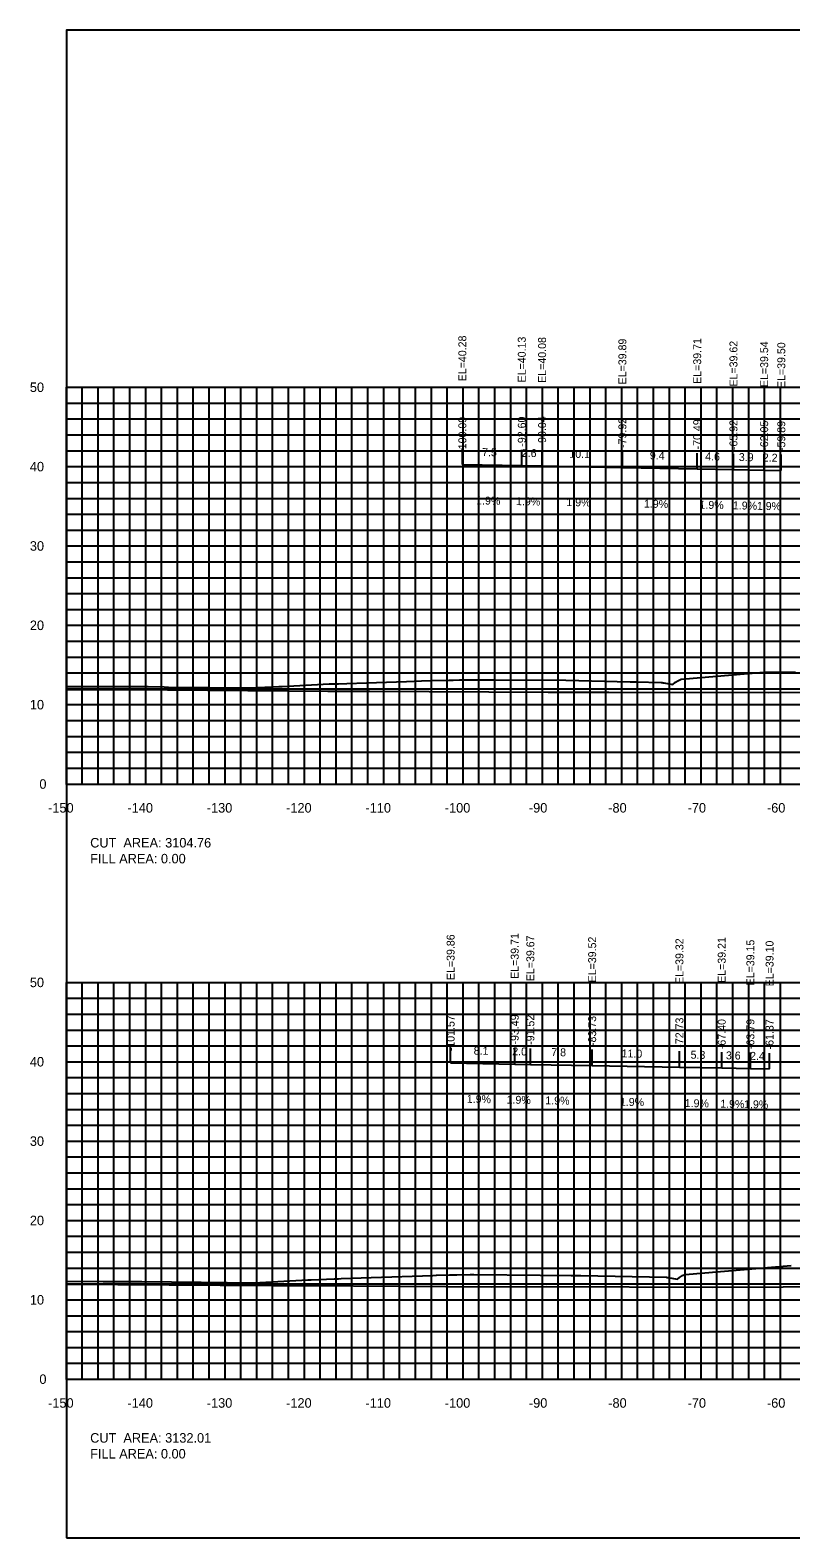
# Model space of a CAD drawing. Extents: x 1800880 to 1818864, y 245271 to 250560.
# Drawn here: x 1810398.3 to 1810494.1, y 250355.3 to 250545.3 of the extents above; entities that cross this region are included whole.
import ezdxf

# ---------------------------------------------------------------- set-up
doc = ezdxf.new("R2010")
doc.units = 0
for name, color, linetype in [('33', 7, 'Continuous'), ('ANNO-TXT', 7, 'Continuous'), ('CL-CNST', 7, 'Continuous'), ('DESIGN - DRAINAGE - Bridges', 7, 'Continuous'), ('DRAINAGETXT', 7, 'Continuous'), ('Level 37', 7, 'Continuous'), ('Level 46', 7, 'Continuous'), ('Level 62', 7, 'Continuous'), ('SHT-BDR', 7, 'Continuous')]:
    doc.layers.add(name, color=color, linetype=linetype)

msp = doc.modelspace()

# ---------------------------------------------------------------- linework, layer by layer
at = {"layer": 'CL-CNST'}
for points in [[(1810402.82, 250462.62), (1810403.63, 250462.62), (1810409.47, 250462.61), (1810412.41, 250462.6), (1810413.12, 250462.6), (1810415.15, 250462.55), (1810415.68, 250462.54), (1810425.94, 250462.42), (1810425.95, 250462.42), (1810426.04, 250462.43), (1810426.05, 250462.43), (1810429.6, 250462.62), (1810429.75, 250462.63), (1810430.02, 250462.63), (1810435.94, 250462.94), (1810436.28, 250462.94), (1810436.44, 250462.94), (1810437, 250462.96), (1810437.1, 250462.96), (1810438.18, 250462.99), (1810440.64, 250463.06), (1810445.67, 250463.25), (1810447.56, 250463.32), (1810448.75, 250463.37), (1810451.01, 250463.41), (1810451.53, 250463.42), (1810451.58, 250463.42), (1810452.39, 250463.44), (1810453.56, 250463.47), (1810456.87, 250463.45), (1810465.78, 250463.39), (1810473.87, 250463.21), (1810474.65, 250463.19), (1810477.79, 250463.12), (1810477.86, 250463.11), (1810477.94, 250463.1), (1810478.01, 250463.09), (1810478.07, 250463.08), (1810478.13, 250463.07), (1810479.24, 250462.88), (1810479.61, 250463.15), (1810479.87, 250463.34), (1810480.31, 250463.55), (1810480.35, 250463.55), (1810490.71, 250464.41), (1810494.71, 250464.43)], [(1810402.82, 250387.67), (1810407.47, 250387.64), (1810410.23, 250387.64), (1810412.32, 250387.63), (1810419.83, 250387.55), (1810426.39, 250387.46), (1810426.44, 250387.46), (1810433.27, 250387.82), (1810433.5, 250387.83), (1810433.67, 250387.83), (1810436.56, 250387.98), (1810436.93, 250387.98), (1810437.06, 250387.98), (1810437.1, 250387.98), (1810437.47, 250387.99), (1810441.25, 250388.11), (1810449.01, 250388.4), (1810449.44, 250388.41), (1810449.45, 250388.41), (1810451.11, 250388.45), (1810451.46, 250388.46), (1810451.71, 250388.46), (1810452.05, 250388.46), (1810453.72, 250388.5), (1810454.17, 250388.51), (1810462.55, 250388.43), (1810466.43, 250388.39), (1810467.65, 250388.37), (1810478.44, 250388.18), (1810478.48, 250388.17), (1810478.55, 250388.15), (1810478.61, 250388.14), (1810479.84, 250387.92), (1810480.11, 250388.12), (1810480.48, 250388.38), (1810480.79, 250388.53), (1810480.81, 250388.53), (1810494.17, 250389.64)]]:
    msp.add_lwpolyline(points, dxfattribs=at)
at = {"layer": 'DESIGN - DRAINAGE - Bridges'}
for p, q in [((1810402.76, 250500.32), (1810402.82, 250500.32)), ((1810402.82, 250450.32), (1810402.82, 250500.32)), ((1810402.76, 250490.32), (1810402.82, 250490.32)), ((1810402.76, 250480.32), (1810402.82, 250480.32)), ((1810402.76, 250470.32), (1810402.82, 250470.32)), ((1810402.76, 250460.32), (1810402.82, 250460.32)), ((1810402.76, 250450.32), (1810402.82, 250450.32)), ((1810402.82, 250450.32), (1810702.82, 250450.32)), ((1810402.82, 250450.26), (1810402.82, 250450.32)), ((1810412.82, 250450.26), (1810412.82, 250450.32)), ((1810422.82, 250450.26), (1810422.82, 250450.32)), ((1810432.82, 250450.26), (1810432.82, 250450.32)), ((1810442.82, 250450.26), (1810442.82, 250450.32)), ((1810452.82, 250450.26), (1810452.82, 250450.32)), ((1810462.82, 250450.26), (1810462.82, 250450.32)), ((1810472.82, 250450.26), (1810472.82, 250450.32)), ((1810482.82, 250450.26), (1810482.82, 250450.32)), ((1810492.82, 250450.26), (1810492.82, 250450.32)), ((1810402.76, 250425.32), (1810402.82, 250425.32)), ((1810402.82, 250375.32), (1810402.82, 250425.32)), ((1810402.76, 250415.32), (1810402.82, 250415.32)), ((1810402.76, 250405.32), (1810402.82, 250405.32)), ((1810402.76, 250395.32), (1810402.82, 250395.32)), ((1810402.76, 250385.32), (1810402.82, 250385.32)), ((1810402.76, 250375.32), (1810402.82, 250375.32)), ((1810402.82, 250375.32), (1810702.82, 250375.32)), ((1810402.82, 250375.26), (1810402.82, 250375.32)), ((1810412.82, 250375.26), (1810412.82, 250375.32)), ((1810422.82, 250375.26), (1810422.82, 250375.32)), ((1810432.82, 250375.26), (1810432.82, 250375.32)), ((1810442.82, 250375.26), (1810442.82, 250375.32)), ((1810452.82, 250375.26), (1810452.82, 250375.32)), ((1810462.82, 250375.26), (1810462.82, 250375.32)), ((1810472.82, 250375.26), (1810472.82, 250375.32)), ((1810482.82, 250375.26), (1810482.82, 250375.32)), ((1810492.82, 250375.26), (1810492.82, 250375.32))]:
    msp.add_line(p, q, dxfattribs=at)
at = {"layer": 'Level 37'}
for p, q in [((1810452.73, 250490.6), (1810452.73, 250492.6)), ((1810460.22, 250490.45), (1810460.22, 250492.45)), ((1810462.78, 250490.41), (1810462.78, 250492.41)), ((1810472.9, 250490.21), (1810472.9, 250492.21)), ((1810482.33, 250490.03), (1810482.33, 250492.03)), ((1810486.9, 250489.94), (1810486.9, 250491.94)), ((1810490.77, 250489.87), (1810490.77, 250491.87)), ((1810492.93, 250489.83), (1810492.93, 250491.83)), ((1810451.25, 250415.19), (1810451.25, 250417.19)), ((1810459.33, 250415.03), (1810459.33, 250417.03)), ((1810461.3, 250414.99), (1810461.3, 250416.99)), ((1810469.09, 250414.85), (1810469.09, 250416.85)), ((1810480.09, 250414.64), (1810480.09, 250416.64)), ((1810485.42, 250414.54), (1810485.42, 250416.54)), ((1810489.03, 250414.47), (1810489.03, 250416.47)), ((1810491.45, 250414.42), (1810491.45, 250416.42))]:
    msp.add_line(p, q, dxfattribs=at)
msp.add_lwpolyline([(1810402.82, 250355.32), (1810702.82, 250355.32), (1810702.82, 250545.32), (1810402.82, 250545.32)], close=True, dxfattribs=at)
at = {"layer": 'Level 46'}
for p, q in [((1810402.82, 250500.32), (1810702.82, 250500.32)), ((1810402.82, 250450.32), (1810402.82, 250500.32)), ((1810404.82, 250450.32), (1810404.82, 250500.32)), ((1810406.82, 250450.32), (1810406.82, 250500.32)), ((1810408.82, 250450.32), (1810408.82, 250500.32)), ((1810410.82, 250450.32), (1810410.82, 250500.32)), ((1810412.82, 250450.32), (1810412.82, 250500.32)), ((1810414.82, 250450.32), (1810414.82, 250500.32)), ((1810416.82, 250450.32), (1810416.82, 250500.32)), ((1810418.82, 250450.32), (1810418.82, 250500.32)), ((1810420.82, 250450.32), (1810420.82, 250500.32)), ((1810422.82, 250450.32), (1810422.82, 250500.32)), ((1810424.82, 250450.32), (1810424.82, 250500.32)), ((1810426.82, 250450.32), (1810426.82, 250500.32)), ((1810428.82, 250450.32), (1810428.82, 250500.32)), ((1810430.82, 250450.32), (1810430.82, 250500.32)), ((1810432.82, 250450.32), (1810432.82, 250500.32)), ((1810434.82, 250450.32), (1810434.82, 250500.32)), ((1810436.82, 250450.32), (1810436.82, 250500.32)), ((1810438.82, 250450.32), (1810438.82, 250500.32)), ((1810440.82, 250450.32), (1810440.82, 250500.32)), ((1810442.82, 250450.32), (1810442.82, 250500.32)), ((1810444.82, 250450.32), (1810444.82, 250500.32)), ((1810446.82, 250450.32), (1810446.82, 250500.32)), ((1810448.82, 250450.32), (1810448.82, 250500.32)), ((1810450.82, 250450.32), (1810450.82, 250500.32)), ((1810452.82, 250450.32), (1810452.82, 250500.32)), ((1810454.82, 250450.32), (1810454.82, 250500.32)), ((1810456.82, 250450.32), (1810456.82, 250500.32)), ((1810458.82, 250450.32), (1810458.82, 250500.32)), ((1810460.82, 250450.32), (1810460.82, 250500.32)), ((1810462.82, 250450.32), (1810462.82, 250500.32)), ((1810464.82, 250450.32), (1810464.82, 250500.32)), ((1810466.82, 250450.32), (1810466.82, 250500.32)), ((1810468.82, 250450.32), (1810468.82, 250500.32)), ((1810470.82, 250450.32), (1810470.82, 250500.32)), ((1810472.82, 250450.32), (1810472.82, 250500.32)), ((1810474.82, 250450.32), (1810474.82, 250500.32)), ((1810476.82, 250450.32), (1810476.82, 250500.32)), ((1810478.82, 250450.32), (1810478.82, 250500.32)), ((1810480.82, 250450.32), (1810480.82, 250500.32)), ((1810482.82, 250450.32), (1810482.82, 250500.32)), ((1810484.82, 250450.32), (1810484.82, 250500.32)), ((1810486.82, 250450.32), (1810486.82, 250500.32)), ((1810488.82, 250450.32), (1810488.82, 250500.32)), ((1810490.82, 250450.32), (1810490.82, 250500.32)), ((1810492.82, 250450.32), (1810492.82, 250500.32)), ((1810402.82, 250498.32), (1810702.82, 250498.32)), ((1810402.82, 250496.32), (1810702.82, 250496.32)), ((1810402.82, 250494.32), (1810702.82, 250494.32)), ((1810402.82, 250492.32), (1810702.82, 250492.32)), ((1810402.82, 250490.32), (1810702.82, 250490.32)), ((1810402.82, 250488.32), (1810702.82, 250488.32)), ((1810402.82, 250486.32), (1810702.82, 250486.32)), ((1810402.82, 250484.32), (1810702.82, 250484.32)), ((1810402.82, 250482.32), (1810702.82, 250482.32)), ((1810402.82, 250480.32), (1810702.82, 250480.32)), ((1810402.82, 250478.32), (1810702.82, 250478.32)), ((1810402.82, 250476.32), (1810702.82, 250476.32)), ((1810402.82, 250474.32), (1810702.82, 250474.32)), ((1810402.82, 250472.32), (1810702.82, 250472.32)), ((1810402.82, 250470.32), (1810702.82, 250470.32)), ((1810402.82, 250468.32), (1810702.82, 250468.32)), ((1810402.82, 250466.32), (1810702.82, 250466.32)), ((1810402.82, 250464.32), (1810702.82, 250464.32)), ((1810402.82, 250462.32), (1810702.82, 250462.32)), ((1810402.82, 250460.32), (1810702.82, 250460.32)), ((1810402.82, 250458.32), (1810702.82, 250458.32)), ((1810402.82, 250456.32), (1810702.82, 250456.32)), ((1810402.82, 250454.32), (1810702.82, 250454.32)), ((1810402.82, 250452.32), (1810702.82, 250452.32)), ((1810402.82, 250450.32), (1810702.82, 250450.32)), ((1810402.82, 250425.32), (1810702.82, 250425.32)), ((1810402.82, 250375.32), (1810402.82, 250425.32)), ((1810404.82, 250375.32), (1810404.82, 250425.32)), ((1810406.82, 250375.32), (1810406.82, 250425.32)), ((1810408.82, 250375.32), (1810408.82, 250425.32)), ((1810410.82, 250375.32), (1810410.82, 250425.32)), ((1810412.82, 250375.32), (1810412.82, 250425.32)), ((1810414.82, 250375.32), (1810414.82, 250425.32)), ((1810416.82, 250375.32), (1810416.82, 250425.32)), ((1810418.82, 250375.32), (1810418.82, 250425.32)), ((1810420.82, 250375.32), (1810420.82, 250425.32)), ((1810422.82, 250375.32), (1810422.82, 250425.32)), ((1810424.82, 250375.32), (1810424.82, 250425.32)), ((1810426.82, 250375.32), (1810426.82, 250425.32)), ((1810428.82, 250375.32), (1810428.82, 250425.32)), ((1810430.82, 250375.32), (1810430.82, 250425.32)), ((1810432.82, 250375.32), (1810432.82, 250425.32)), ((1810434.82, 250375.32), (1810434.82, 250425.32)), ((1810436.82, 250375.32), (1810436.82, 250425.32)), ((1810438.82, 250375.32), (1810438.82, 250425.32)), ((1810440.82, 250375.32), (1810440.82, 250425.32)), ((1810442.82, 250375.32), (1810442.82, 250425.32)), ((1810444.82, 250375.32), (1810444.82, 250425.32)), ((1810446.82, 250375.32), (1810446.82, 250425.32)), ((1810448.82, 250375.32), (1810448.82, 250425.32)), ((1810450.82, 250375.32), (1810450.82, 250425.32)), ((1810452.82, 250375.32), (1810452.82, 250425.32)), ((1810454.82, 250375.32), (1810454.82, 250425.32)), ((1810456.82, 250375.32), (1810456.82, 250425.32)), ((1810458.82, 250375.32), (1810458.82, 250425.32)), ((1810460.82, 250375.32), (1810460.82, 250425.32)), ((1810462.82, 250375.32), (1810462.82, 250425.32)), ((1810464.82, 250375.32), (1810464.82, 250425.32)), ((1810466.82, 250375.32), (1810466.82, 250425.32)), ((1810468.82, 250375.32), (1810468.82, 250425.32)), ((1810470.82, 250375.32), (1810470.82, 250425.32)), ((1810472.82, 250375.32), (1810472.82, 250425.32)), ((1810474.82, 250375.32), (1810474.82, 250425.32)), ((1810476.82, 250375.32), (1810476.82, 250425.32)), ((1810478.82, 250375.32), (1810478.82, 250425.32)), ((1810480.82, 250375.32), (1810480.82, 250425.32)), ((1810482.82, 250375.32), (1810482.82, 250425.32)), ((1810484.82, 250375.32), (1810484.82, 250425.32)), ((1810486.82, 250375.32), (1810486.82, 250425.32)), ((1810488.82, 250375.32), (1810488.82, 250425.32)), ((1810490.82, 250375.32), (1810490.82, 250425.32)), ((1810492.82, 250375.32), (1810492.82, 250425.32)), ((1810402.82, 250423.32), (1810702.82, 250423.32)), ((1810402.82, 250421.32), (1810702.82, 250421.32)), ((1810402.82, 250419.32), (1810702.82, 250419.32)), ((1810402.82, 250417.32), (1810702.82, 250417.32)), ((1810402.82, 250415.32), (1810702.82, 250415.32)), ((1810402.82, 250413.32), (1810702.82, 250413.32)), ((1810402.82, 250411.32), (1810702.82, 250411.32)), ((1810402.82, 250409.32), (1810702.82, 250409.32)), ((1810402.82, 250407.32), (1810702.82, 250407.32)), ((1810402.82, 250405.32), (1810702.82, 250405.32)), ((1810402.82, 250403.32), (1810702.82, 250403.32)), ((1810402.82, 250401.32), (1810702.82, 250401.32)), ((1810402.82, 250399.32), (1810702.82, 250399.32)), ((1810402.82, 250397.32), (1810702.82, 250397.32)), ((1810402.82, 250395.32), (1810702.82, 250395.32)), ((1810402.82, 250393.32), (1810702.82, 250393.32)), ((1810402.82, 250391.32), (1810702.82, 250391.32)), ((1810402.82, 250389.32), (1810702.82, 250389.32)), ((1810402.82, 250387.32), (1810702.82, 250387.32)), ((1810402.82, 250385.32), (1810702.82, 250385.32)), ((1810402.82, 250383.32), (1810702.82, 250383.32)), ((1810402.82, 250381.32), (1810702.82, 250381.32)), ((1810402.82, 250379.32), (1810702.82, 250379.32)), ((1810402.82, 250377.32), (1810702.82, 250377.32)), ((1810402.82, 250375.32), (1810702.82, 250375.32))]:
    msp.add_line(p, q, dxfattribs=at)
at = {"layer": 'Level 62'}
for points in [[(1810452.73, 250490.6), (1810460.22, 250490.45), (1810462.78, 250490.41), (1810472.9, 250490.21), (1810482.33, 250490.03), (1810486.9, 250489.94), (1810490.77, 250489.87), (1810492.93, 250489.83)], [(1810402.82, 250462.24), (1810408.02, 250462.21), (1810410.52, 250462.21), (1810435.77, 250462.03), (1810441.07, 250462.04), (1810463.53, 250461.88), (1810471.19, 250461.91), (1810491.28, 250461.84), (1810500.95, 250461.89), (1810519.04, 250461.91), (1810530.44, 250461.97), (1810546.79, 250461.69), (1810559.71, 250461.76), (1810574.55, 250461.92), (1810588.23, 250461.83), (1810602.3, 250461.92), (1810615.76, 250462.15), (1810630.06, 250462.23), (1810643.25, 250461.87), (1810657.81, 250461.97), (1810676.99, 250461.3), (1810685.57, 250461.36), (1810702.82, 250461.36)], [(1810451.25, 250415.19), (1810459.33, 250415.03), (1810461.3, 250414.99), (1810469.09, 250414.85), (1810480.09, 250414.64), (1810485.42, 250414.54), (1810489.03, 250414.47), (1810491.45, 250414.42)], [(1810402.82, 250387.3), (1810428.69, 250387.11), (1810433.15, 250387.12), (1810456.44, 250386.96), (1810463.32, 250386.98), (1810484.2, 250386.91), (1810493.15, 250386.96), (1810511.95, 250386.98), (1810522.69, 250387.04), (1810539.71, 250386.74), (1810552, 250386.81), (1810567.46, 250386.98), (1810581.72, 250386.88), (1810595.22, 250386.97), (1810609.26, 250387.2), (1810622.97, 250387.29), (1810636.76, 250386.91), (1810650.73, 250387), (1810670.8, 250386.3), (1810678.48, 250386.36), (1810698.87, 250386.36), (1810702.82, 250386.38)]]:
    msp.add_lwpolyline(points, dxfattribs=at)

# ---------------------------------------------------------------- texts
for s, p in [('-150', (1810400.52, 250446.72)), ('-140', (1810410.52, 250446.72)), ('-130', (1810420.52, 250446.72)), ('-120', (1810430.52, 250446.72)), ('-110', (1810440.52, 250446.72)), ('-100', (1810450.52, 250446.72)), ('-90', (1810461.12, 250446.72)), ('-80', (1810471.12, 250446.72)), ('-70', (1810481.12, 250446.72)), ('-60', (1810491.12, 250446.72)), ('-150', (1810400.52, 250371.72)), ('-140', (1810410.52, 250371.72)), ('-130', (1810420.52, 250371.72)), ('-120', (1810430.52, 250371.72)), ('-110', (1810440.52, 250371.72)), ('-100', (1810450.52, 250371.72)), ('-90', (1810461.12, 250371.72)), ('-80', (1810471.12, 250371.72)), ('-70', (1810481.12, 250371.72)), ('-60', (1810491.12, 250371.72))]:
    msp.add_text(s, height=1.2).set_placement(p)
at = {"layer": '33'}
for s, p in [('50', (1810398.22, 250499.72)), ('40', (1810398.22, 250489.72)), ('30', (1810398.22, 250479.72)), ('20', (1810398.22, 250469.72)), ('10', (1810398.22, 250459.72)), ('0', (1810399.42, 250449.72)), ('50', (1810398.22, 250424.72)), ('40', (1810398.22, 250414.72)), ('30', (1810398.22, 250404.72)), ('20', (1810398.22, 250394.72)), ('10', (1810398.22, 250384.72)), ('0', (1810399.42, 250374.72))]:
    msp.add_text(s, height=1.2, dxfattribs=at).set_placement(p)
at = {"layer": 'ANNO-TXT'}
for s, rotation, p in [('7.5', 358.9008, (1810455.21, 250491.65)), ('2.6', 358.9008, (1810460.21, 250491.55)), ('10.1', 358.9008, (1810466.21, 250491.44)), ('9.4', 358.8964, (1810476.35, 250491.24)), ('4.6', 358.8964, (1810483.33, 250491.11)), ('3.9', 358.8964, (1810487.57, 250491.03)), ('2.2', 358.8964, (1810490.59, 250490.97)), ('1.9%', 358.9008, (1810454.46, 250485.56)), ('1.9%', 358.9008, (1810459.49, 250485.47)), ('1.9%', 358.9008, (1810465.83, 250485.35)), ('1.9%', 358.8964, (1810475.61, 250485.16)), ('1.9%', 358.8964, (1810482.61, 250485.02)), ('1.9%', 358.8964, (1810486.82, 250484.94)), ('1.9%', 358.8964, (1810489.84, 250484.88)), ('8.1', 358.9139, (1810454.15, 250416.23)), ('2.0', 358.9139, (1810459.01, 250416.14)), ('7.8', 358.9139, (1810463.93, 250416.04)), ('11.0', 358.9095, (1810472.79, 250415.88)), ('5.3', 358.9095, (1810481.49, 250415.71)), ('3.6', 358.9095, (1810485.94, 250415.63)), ('2.4', 358.9095, (1810488.98, 250415.57)), ('1.9%', 358.9139, (1810453.28, 250410.15)), ('1.9%', 358.9139, (1810458.3, 250410.05)), ('1.9%', 358.9139, (1810463.18, 250409.96)), ('1.9%', 358.9095, (1810472.58, 250409.78)), ('1.9%', 358.9095, (1810480.75, 250409.62)), ('1.9%', 358.9095, (1810485.22, 250409.54)), ('1.9%', 358.9095, (1810488.23, 250409.48))]:
    msp.add_text(s, height=1, rotation=rotation, dxfattribs=at).set_placement(p)
at = {"layer": 'DESIGN - DRAINAGE - Bridges'}
for p in [(1810402.82, 250450.32), (1810402.82, 250375.32)]:
    msp.add_text('-', height=0.0001, dxfattribs=at).set_placement(p)
at = {"layer": 'DRAINAGETXT'}
for s, p in [('CUT  AREA: 3104.76', (1810405.82, 250442.32)), ('FILL AREA: 0.00', (1810405.82, 250440.32)), ('CUT  AREA: 3132.01', (1810405.82, 250367.32)), ('FILL AREA: 0.00', (1810405.82, 250365.32))]:
    msp.add_text(s, height=1.2, dxfattribs=at).set_placement(p)
at = {"layer": 'SHT-BDR'}
for s, p in [('EL=40.28', (1810453.23, 250501.07)), ('EL=40.13', (1810460.72, 250500.93)), ('EL=40.08', (1810463.28, 250500.88)), ('EL=39.89', (1810473.4, 250500.68)), ('EL=39.71', (1810482.83, 250500.75)), ('EL=39.62', (1810487.4, 250500.41)), ('EL=39.54', (1810491.27, 250500.34)), ('EL=39.50', (1810493.43, 250500.22)), ('-100.09', (1810453.23, 250492.06)), ('-92.60', (1810460.72, 250492.83)), ('-90.04', (1810463.28, 250492.86)), ('-79.92', (1810473.4, 250492.67)), ('-70.49', (1810482.83, 250492.49)), ('-65.92', (1810487.4, 250492.4)), ('-62.05', (1810491.27, 250492.32)), ('-59.89', (1810493.43, 250492.28)), ('EL=39.71', (1810459.83, 250425.76)), ('EL=39.86', (1810451.75, 250425.61)), ('EL=39.67', (1810461.8, 250425.47)), ('EL=39.52', (1810469.59, 250425.32)), ('EL=39.32', (1810480.59, 250425.11)), ('EL=39.21', (1810485.92, 250425.26)), ('EL=39.15', (1810489.53, 250424.94)), ('EL=39.10', (1810491.95, 250424.82)), ('-101.57', (1810451.75, 250416.65)), ('-93.49', (1810459.83, 250417.49)), ('-91.52', (1810461.8, 250417.45)), ('-83.73', (1810469.59, 250417.3)), ('-72.73', (1810480.59, 250417.09)), ('-67.40', (1810485.92, 250416.91)), ('-63.79', (1810489.53, 250416.92)), ('-61.37', (1810491.95, 250416.88))]:
    msp.add_text(s, height=1, rotation=90, dxfattribs=at).set_placement(p)

doc.saveas('drawing.dxf')
